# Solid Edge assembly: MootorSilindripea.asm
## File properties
Author: Türk
Template: Iso Assembly.asm
Last saved by: Türk
Revision: 31
Application: Solid Edge
Username: Türk
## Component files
Klapikoostu_mir4.asm
Klapikoostu_mir3.asm
Klapikoostu_mir2.asm
Klapikoostu_mir1.asm
Klapikoostu_mir.asm
Silindripea.par
llikoostu.asm
llikoostu_mir.asm
Sildindripeakate.par
Klapikoostu.asm
Sisslasekkoostu.asm
Klapikoostu_mir5.asm
Klapikoostu_mir6.asm
Klapikoostu_mir21.asm
Klapikoostu_mir41.asm
Klapikoostu_mir7.asm
Klapikoostu_mir8.asm
Klapikoostu_mir9.asm
Klapikoostu_mir11.asm
Klapikoostu_mir10.asm
Klapikoostu_mir31.asm
ljalase.par
llihoidja.asm
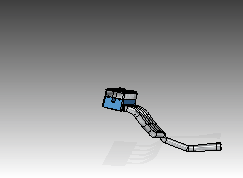
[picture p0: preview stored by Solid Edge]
